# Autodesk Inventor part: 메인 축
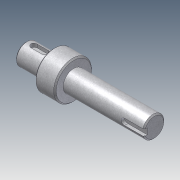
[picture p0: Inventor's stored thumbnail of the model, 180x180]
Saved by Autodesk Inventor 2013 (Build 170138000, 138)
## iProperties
Company: 한국ATC센터
Created: 2014-10
Part Number: 메인 축
Document SubType Name: Modeling
Designer: KYOUNG IL JANG
Density: 7.85 g/cm^3
Mass: 229.947 g
Surface Area: 74.3518 cm^2
Volume: 29.2926 cm^3
Material: 강철
Author: KYOUNG IL JANG
Revision Number: 1
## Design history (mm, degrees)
sketch "스케치1"
  geometry: L1 (10.497, -57.5)-(112.497, -57.5); L2 (10.497, -66)-(32.497, -66); L3 (32.497, -72.5)-(46.5, -72.5); L4 (46.5, -66)-(112.497, -66); L5 (112.497, -66)-(112.497, -57.5); L6 (10.497, -66)-(10.497, -57.5); L7 (46.5, -69.749)-(46.5, -45.251) reference; L8 (46.5, -72.5)-(46.5, -66); L9 (32.497, -72.5)-(32.497, -66); L10 (32.497, -35)-(32.497, -80) reference; 3 further points
  constraints: 16 end point, 3 point on line, 2 parallel, 2 perpendicular, 1 collinear, 1 horizontal, 1 midpoint
  dimensions: "d0" = 17 diameter of L4 L1; "d1" = 30 diameter of L3 L1; "d2" = 22 distance of L2.start L2.end; "d3" = 65.99692 distance of L4.start L4.end (derived); "d5" = 17 diameter of L2 L1; "d19" = 80 distance between parallel lines of L5 L9
revolve "회전1" sketch "스케치1" stored, may be unused: angle "d4" = 90 deg
chamfer "모따기1" distance "d6" = 1; stored, may be unused: second distance "d7" = 2, angle "d8" = 45 deg
node "작업 평면1"
sketch "스케치2"
  geometry: L1 (-11, -7.5)-(-11, 7.5) reference; L2 (-4.5, 2.5)-(4.5, 2.5); L3 (4.5, -2.5)-(-4.5, -2.5); A1 r 2.5 centre (4.5, 0) between (4.5, -2.5) and (4.5, 2.5); A2 r 2.5 centre (-4.5, 0) between (-4.5, 2.5) and (-4.5, -2.5); 2 further points
  constraints: 4 end point, 4 point on circle, 4 tangent, 2 centre point, 1 horizontal alignment, 1 midpoint, 1 parallel, 1 perpendicular
  dimensions: "d9" = 5 distance between parallel lines of L3 L2; "d10" = 14 dimension on A1 A2; "d11" = 4 distance edge to line of A2 L1
extrude "돌출1" cut sketch "스케치2" distance "d12" = 3; taper "d13" = 0 deg
node "작업 평면2"
sketch "스케치3"
  geometry: L1 (32.998, 7.5)-(32.998, -7.5) reference; L2 (32.998, 2.5)-(17.498, 2.5); L3 (17.498, -2.5)-(32.998, -2.5); A1 r 2.5 centre (17.498, 0) between (17.498, 2.5) and (17.498, -2.5); 2 further points
  constraints: 4 end point, 2 perpendicular, 2 point on circle, 2 point on line, 2 tangent, 1 centre point, 1 horizontal alignment, 1 midpoint
  dimensions: "d14" = 5 distance between parallel lines of L3 L2; "d15" = 18 dimension on A1 L1
extrude "돌출2" cut sketch "스케치3" distance "d16" = 3; taper "d17" = 0 deg
node "솔리드1"
node "참조4"
node "참조5"
